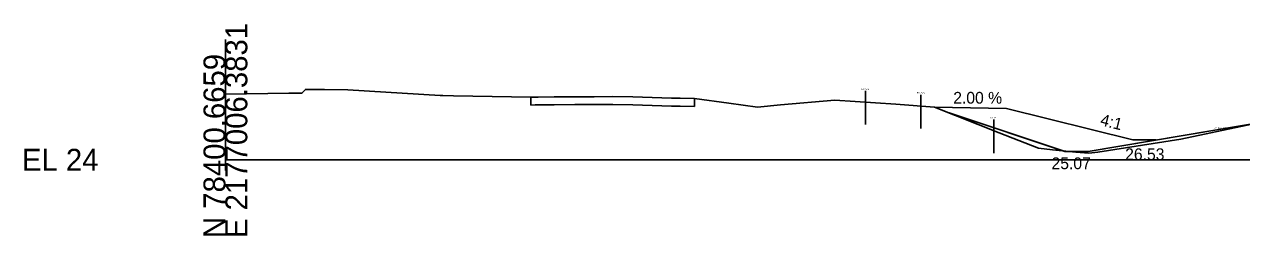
# Model space of a CAD drawing. Extents: x 2177029 to 2201446, y 59897 to 78390.
# Drawn here: x 2201017 to 2201172.6, y 64397.6 to 64424.6 of the extents above; entities that cross this region are included whole.
import ezdxf

# ---------------------------------------------------------------- set-up
doc = ezdxf.new("R2010")
doc.units = 0
for name, color, linetype in [('Exist Cross Section Cell', 7, 'Continuous'), ('Exist PHM Roadway Shape', 7, 'Continuous'), ('Exist XS Ground Line', 7, 'Continuous'), ('Old_Level_1', 7, 'Continuous'), ('Old_Level_3', 7, 'Continuous'), ('Prop CMT Pvmt Surface Shoulder', 7, 'Continuous'), ('Prop CMT Pvmt Wedge Surface 1', 7, 'Continuous'), ('Prop CMT Top Wall Envelope', 7, 'Continuous'), ('Prop Hatching', 7, 'Continuous'), ('Prop XS Earthwork Shape', 7, 'Continuous'), ('Prop XS Side Slope Text', 7, 'Continuous')]:
    doc.layers.add(name, color=color, linetype=linetype)

msp = doc.modelspace()

# ---------------------------------------------------------------- linework, layer by layer
at = {"layer": 'Exist Cross Section Cell'}
msp.add_line((2201042.73, 64407.31), (2201242.73, 64407.31), dxfattribs=at)
at = {"layer": 'Exist XS Ground Line'}
msp.add_lwpolyline([(2201042.73, 64415.68), (2201050.83, 64415.81), (2201051.96, 64415.81), (2201052.51, 64415.8), (2201052.95, 64416.3), (2201055.4, 64416.28), (2201058.37, 64416.24), (2201070.19, 64415.54), (2201070.52, 64415.52), (2201071.89, 64415.49), (2201081.76, 64415.29), (2201082.31, 64415.31), (2201082.69, 64415.31), (2201084.75, 64415.35), (2201087.4, 64415.36), (2201089.87, 64415.37), (2201092.25, 64415.39), (2201094.81, 64415.34), (2201097.25, 64415.26), (2201099.75, 64415.18), (2201100.83, 64415.17), (2201102.66, 64415.13), (2201107.06, 64414.54), (2201110.7, 64414.04), (2201113.64, 64414.32), (2201120.6, 64414.93), (2201128.41, 64414.41), (2201133.34, 64414.05), (2201141.58, 64410.77), (2201146.61, 64408.81), (2201148.41, 64408.57), (2201151.39, 64408.3), (2201153.05, 64408.14), (2201154.22, 64408.3), (2201164.8, 64409.93), (2201172.5, 64411.56), (2201173.73, 64411.8)], dxfattribs=at)
at = {"layer": 'Old_Level_1'}
for p, q in [((2201133.34, 64414.05), (2201142.55, 64413.87)), ((2201142.55, 64413.87), (2201158.66, 64409.84)), ((2201158.66, 64409.84), (2201161.66, 64409.84))]:
    msp.add_line(p, q, dxfattribs=at)
at = {"layer": 'Old_Level_3'}
msp.add_line((2201042.73, 64405.94), (2201042.73, 64422.68), dxfattribs=at)
at = {"layer": 'Prop CMT Pvmt Surface Shoulder'}
msp.add_line((2201140.92, 64412.45), (2201140.92, 64408.14), dxfattribs=at)
at = {"layer": 'Prop CMT Pvmt Wedge Surface 1'}
for p, q in [((2201081.76, 64414.29), (2201081.76, 64415.29)), ((2201087.4, 64414.36), (2201089.87, 64414.37)), ((2201089.87, 64414.37), (2201092.25, 64414.39)), ((2201092.25, 64414.39), (2201094.81, 64414.34)), ((2201102.66, 64415.13), (2201102.66, 64414.13)), ((2201081.76, 64414.29), (2201082.31, 64414.31)), ((2201082.31, 64414.31), (2201082.69, 64414.31)), ((2201082.69, 64414.31), (2201084.75, 64414.35)), ((2201084.75, 64414.35), (2201087.4, 64414.36)), ((2201094.81, 64414.34), (2201097.25, 64414.26)), ((2201097.25, 64414.26), (2201099.75, 64414.18)), ((2201099.75, 64414.18), (2201100.83, 64414.17)), ((2201100.83, 64414.17), (2201102.66, 64414.13))]:
    msp.add_line(p, q, dxfattribs=at)
at = {"layer": 'Prop Hatching'}
for p, q in [((2201149.99, 64408.38), (2201135.2, 64413.31)), ((2201152.99, 64408.38), (2201149.99, 64408.38))]:
    msp.add_line(p, q, dxfattribs=at)
msp.add_lwpolyline([(2201178.72, 64412.46), (2201176.72, 64412.38), (2201152.99, 64408.38)], dxfattribs=at)
at = {"layer": 'Prop XS Earthwork Shape'}
for p, q in [((2201124.51, 64416.1), (2201124.51, 64411.8)), ((2201131.58, 64415.61), (2201131.58, 64411.31))]:
    msp.add_line(p, q, dxfattribs=at)
at = {"layer": 'Prop XS Side Slope Text'}
for points in [[(2201141.58, 64410.77), (2201146.61, 64408.81), (2201148.41, 64408.57), (2201149.79, 64408.45), (2201135.2, 64413.31)], [(2201151.39, 64408.3), (2201153.05, 64408.14), (2201154.22, 64408.3), (2201164.8, 64409.93), (2201172.5, 64411.56), (2201173.73, 64411.8), (2201174.66, 64411.88), (2201174.24, 64411.96), (2201152.99, 64408.38), (2201150.5, 64408.38)], [(2201149.99, 64408.38), (2201149.79, 64408.45), (2201150.5, 64408.38)]]:
    msp.add_lwpolyline(points, close=True, dxfattribs=at)

# ---------------------------------------------------------------- texts
at = {"layer": 'Exist Cross Section Cell'}
for s, p in [('E 2177006.3831', (2201045.53, 64397.31)), ('N 78400.6659', (2201042.73, 64397.31))]:
    msp.add_text(s, height=2.8, rotation=90, dxfattribs=at).set_placement(p)
msp.add_text('EL 24', height=2.8, dxfattribs=at).set_placement((2201016.73, 64405.91))
at = {"layer": 'Exist PHM Roadway Shape'}
msp.add_text('LT_Sub_OSS_DLT', height=0.2, dxfattribs=at).set_placement((2201169.06, 64411.25))
at = {"layer": 'Old_Level_1'}
for s, p in [('2.00 %', (2201135.73, 64414.48)), ('26.53', (2201157.7, 64407.27))]:
    msp.add_text(s, height=1.5, dxfattribs=at).set_placement(p)
msp.add_text('4:1', height=1.5, rotation=345.9635, dxfattribs=at).set_placement((2201154.42, 64411.75))
at = {"layer": 'Prop CMT Pvmt Surface Shoulder'}
msp.add_text('EX. W.L.', height=0.2, dxfattribs=at).set_placement((2201140.42, 64412.59))
at = {"layer": 'Prop CMT Top Wall Envelope'}
for s, height, p in [('-', 0.0001, (2201042.73, 64407.31)), ('-', 0.0001, (2201042.73, 64407.31)), ('25.07', 1.5, (2201148.29, 64406.11))]:
    msp.add_text(s, height=height, dxfattribs=at).set_placement(p)
at = {"layer": 'Prop XS Earthwork Shape'}
for p in [(2201124.01, 64416.24), (2201131.09, 64415.75)]:
    msp.add_text('EX. S.S.', height=0.2, dxfattribs=at).set_placement(p)

doc.saveas('drawing.dxf')
